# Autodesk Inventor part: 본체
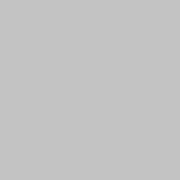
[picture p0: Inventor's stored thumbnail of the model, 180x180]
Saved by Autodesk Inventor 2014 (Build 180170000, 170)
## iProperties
Created: 2016-01
Part Number: 본체
Material: 일반
Document SubType Name: Modeling
Designer: basic
Density: 1 g/cm^3
Appearance: 기본값
Author: basic
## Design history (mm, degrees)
